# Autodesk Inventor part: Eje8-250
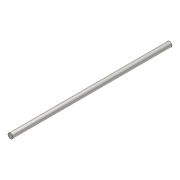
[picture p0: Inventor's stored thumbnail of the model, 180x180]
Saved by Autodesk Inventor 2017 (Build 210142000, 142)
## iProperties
Created: 2018-08
Part Number: Eje8-250
Material: Stainless Steel AISI 304
Document SubType Name: Modeling
Designer: JK
Density: 8 g/cm^3
Appearance: Chrome - Satin
Author: JK
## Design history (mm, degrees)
sketch "Sketch1"
  geometry: C1 r 4 at (0, 0); 1 further point
  constraints: 1 centre point, 1 coincident
  dimensions: "d0" = 8 diameter of C1
extrude "Extrusion1" new body sketch "Sketch1" distance "d1" = 250; taper "d2" = 0 deg
body "Solid1"
